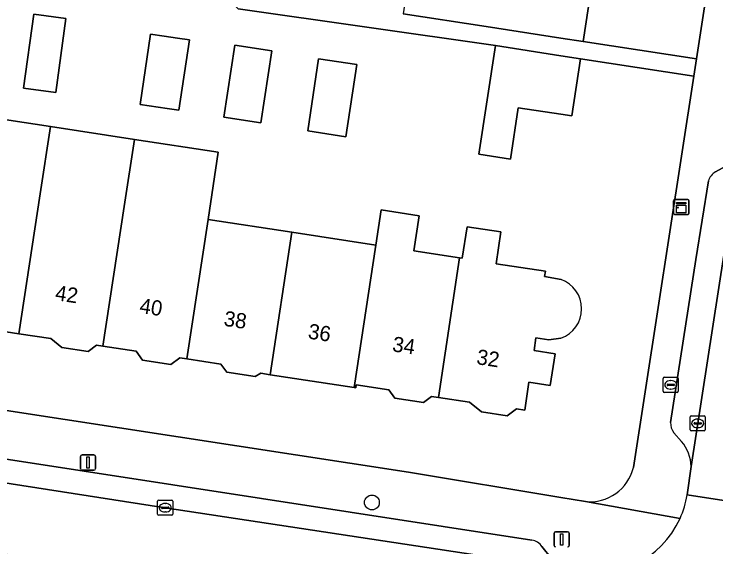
# Model space of a CAD drawing. Extents: x 161483 to 162250, y 379484 to 380833.
# Drawn here: x 161963.9 to 162010.23, y 380537.71 to 380572.87 of the extents above; entities that cross this region are included whole.
import ezdxf

# ---------------------------------------------------------------- set-up
doc = ezdxf.new("R2010")
doc.units = 0
for name, color, linetype in [('IMGEO_Boom', 7, 'Continuous'), ('IMGEO_Brandkraan', 7, 'Continuous'), ('IMGEO_Erf', 7, 'Continuous'), ('IMGEO_Kast', 7, 'Continuous'), ('IMGEO_Kolk', 7, 'Continuous'), ('IMGEO_Lichtmast', 7, 'Continuous'), ('IMGEO_Pand', 7, 'Continuous'), ('IMGEO_Pand_nummerreeks', 7, 'Continuous'), ('IMGEO_Parkeervlak_open', 7, 'Continuous'), ('IMGEO_Rijbaan_lokaal_open', 7, 'Continuous'), ('IMGEO_Voetpad_open', 7, 'Continuous')]:
    doc.layers.add(name, color=color, linetype=linetype)

msp = doc.modelspace()

# ---------------------------------------------------------------- linework, layer by layer
at = {"layer": 'IMGEO_Boom'}
msp.add_circle((161987.521, 380540.644), 0.489, dxfattribs=at)
at = {"layer": 'IMGEO_Brandkraan'}
for p, q in [((162006.744, 380547.979), (162006.744, 380548.831)), ((162006.819, 380548.905), (162007.671, 380548.905)), ((162007.745, 380548.831), (162007.745, 380547.979)), ((162007.003, 380548.399), (162007.003, 380548.411)), ((162007.441, 380548.362), (162007.043, 380548.362)), ((162007.046, 380548.448), (162007.444, 380548.448)), ((162007.232, 380548.685), (162007.257, 380548.685)), ((162007.487, 380548.411), (162007.487, 380548.399)), ((162007.671, 380547.905), (162006.819, 380547.905)), ((162007.255, 380548.125), (162007.23, 380548.125))]:
    msp.add_line(p, q, dxfattribs=at)
for points in [[(162006.744, 380547.979), (162006.744, 380548.831)], [(162006.819, 380548.905), (162007.671, 380548.905)], [(162007.745, 380548.831), (162007.745, 380547.979)], [(162007.671, 380547.905), (162006.819, 380547.905)]]:
    msp.add_lwpolyline(points, dxfattribs=at)
for centre, radius, start, end in [((162006.821, 380548.829), 0.0765, 91.552, 178.448), ((162006.821, 380548.829), 0.0765, 91.552, 178.448), ((162007.669, 380548.829), 0.0765, 1.552, 88.448), ((162007.669, 380548.829), 0.0765, 1.552, 88.448), ((162007.043, 380548.408), 0.0403, 85.8775, 175.7526), ((162007.04, 380548.398), 0.0366, 178.938, 274.7102), ((162007.444, 380548.405), 0.043, 264.8664, 352.4533), ((162007.448, 380548.41), 0.0386, 1.7309, 96.639), ((162006.821, 380547.981), 0.0765, 181.552, 268.448), ((162006.821, 380547.981), 0.0765, 181.552, 268.448), ((162007.669, 380547.981), 0.0765, 271.552, 358.448), ((162007.669, 380547.981), 0.0765, 271.552, 358.448)]:
    msp.add_arc(centre, radius, start, end, dxfattribs=at)
for centre, major_axis, ratio, start_param, end_param in [((162007.231, 380548.405), (-0.387, 0.002), 0.722429, 4.712389, 7.853982), ((162007.256, 380548.405), (-0.39, 0.002), 0.717154, 1.570796, 4.712389)]:
    msp.add_ellipse(centre, major_axis=major_axis, ratio=ratio, start_param=start_param, end_param=end_param, dxfattribs=at)
at = {"layer": 'IMGEO_Erf'}
for points in [[(162001.825, 380573.376), (162001.469, 380571.06), (162008.935, 380569.909), (162019.94, 380641.308)], [(162004.779, 380542.949), (162008.76, 380568.777), (162001.293, 380569.928), (162000.713, 380566.149), (162000, 380566.259), (161997.184, 380566.691), (161996.663, 380563.299), (161994.567, 380563.62), (161995.667, 380570.791), (161978.692, 380573.217), (161972.841, 380578.787), (161972.586, 380577.129), (161971.639, 380576.511), (161968.421, 380577.007), (161969.225, 380582.226), (161964.224, 380587.502), (161963.937, 380589.722), (161969.705, 380626.52)], [(161960.773, 380566.29), (161966.308, 380565.444), (161971.844, 380564.598), (161977.38, 380563.752), (161976.703, 380559.32), (161982.238, 380558.474), (161987.774, 380557.628), (161988.129, 380559.952), (161990.638, 380559.569), (161990.283, 380557.244), (161993.31, 380556.781), (161993.483, 380556.755), (161993.802, 380558.84), (161996.036, 380558.498), (161995.715, 380556.4), (161998.975, 380555.902), (161998.923, 380555.56), (162000.002, 380555.36)], [(162000, 380551.488), (161999.206, 380551.367), (161998.346, 380551.499), (161998.22, 380550.674), (161999.614, 380550.461), (161999.293, 380548.361), (161997.887, 380548.576), (161997.606, 380546.739), (161997.065, 380546.822), (161996.44, 380546.363), (161994.761, 380546.619), (161993.961, 380547.261), (161991.905, 380547.575), (161991.459, 380547.643), (161990.917, 380547.245), (161989.04, 380547.532), (161988.637, 380548.08), (161986.484, 380548.409), (161986.454, 380548.211), (161986.339, 380548.229), (161980.803, 380549.074), (161980.19, 380549.168), (161979.812, 380548.947), (161977.943, 380549.232), (161977.545, 380549.774), (161975.297, 380550.118), (161974.85, 380550.186), (161974.254, 380549.748), (161972.38, 380550.035), (161971.95, 380550.619), (161969.762, 380550.954), (161969.334, 380551.019), (161968.785, 380550.615), (161967.059, 380550.879), (161966.337, 380551.457), (161964.223, 380551.78), (161961.813, 380552.149)], [(161963.411, 380546.705), (161989.926, 380542.639), (162000, 380540.965), (162001.608, 380540.698)]]:
    msp.add_lwpolyline(points, dxfattribs=at)
for points in [[(161967.316, 380572.573), (161966.652, 380567.691), (161964.534, 380567.979), (161965.198, 380572.861)], [(161973.801, 380571.411), (161974.698, 380571.279), (161975.485, 380571.164), (161974.776, 380566.522), (161974.016, 380566.638), (161972.222, 380566.912), (161972.904, 380571.542)], [(161980.909, 380570.448), (161980.183, 380565.688), (161977.741, 380566.061), (161978.468, 380570.821)], [(161986.523, 380569.533), (161985.797, 380564.776), (161983.284, 380565.16), (161983.986, 380569.92)]]:
    msp.add_lwpolyline(points, close=True, dxfattribs=at)
for centre, radius, start, end in [((161999.303, 380553.424), 2.058, 289.7959, 70.1449), ((162001.886, 380543.666), 2.981, 264.6501, 346.0895)]:
    msp.add_arc(centre, radius, start, end, dxfattribs=at)
at = {"layer": 'IMGEO_Kast'}
for p, q in [((162007.436, 380559.713), (162007.436, 380560.554)), ((162007.436, 380560.554), (162007.436, 380559.713)), ((162007.511, 380560.638), (162008.352, 380560.638)), ((162008.352, 380560.638), (162007.511, 380560.638)), ((162008.436, 380560.563), (162008.436, 380559.722)), ((162008.436, 380559.722), (162008.436, 380560.563)), ((162008.361, 380559.638), (162007.52, 380559.638)), ((162007.52, 380559.638), (162008.361, 380559.638))]:
    msp.add_line(p, q, dxfattribs=at)
for points in [[(162007.631, 380560.428), (162008.231, 380560.428), (162008.231, 380560.343), (162007.631, 380560.343), (162007.631, 380560.428)], [(162007.631, 380560.253), (162008.231, 380560.253), (162008.231, 380559.764), (162007.631, 380559.764), (162007.631, 380560.253)]]:
    msp.add_lwpolyline(points, dxfattribs=at)
msp.add_circle((162007.715, 380560.102), 0.0377, dxfattribs=at)
for centre, start, end in [((162007.514, 380560.56), 92.4484, 184.2845), ((162007.514, 380560.56), 92.4484, 184.2845), ((162008.358, 380560.56), 2.4484, 94.2845), ((162008.358, 380560.56), 2.4484, 94.2845), ((162007.514, 380559.716), 182.4484, 274.2845), ((162007.514, 380559.716), 182.4484, 274.2845), ((162008.358, 380559.716), 272.4484, 4.2845), ((162008.358, 380559.716), 272.4484, 4.2845)]:
    msp.add_arc(centre, 0.0779, start, end, dxfattribs=at)
at = {"layer": 'IMGEO_Kolk'}
for p, q in [((162008.524, 380545.437), (162008.524, 380546.289)), ((162008.599, 380546.363), (162009.451, 380546.363)), ((162009.012, 380546.143), (162009.037, 380546.143)), ((162009.525, 380546.289), (162009.525, 380545.437)), ((162008.783, 380545.857), (162008.783, 380545.869)), ((162009.221, 380545.82), (162008.823, 380545.82)), ((162008.826, 380545.906), (162009.224, 380545.906)), ((162009.035, 380545.583), (162009.01, 380545.583)), ((162009.267, 380545.869), (162009.267, 380545.857)), ((162009.451, 380545.363), (162008.599, 380545.363)), ((161973.378, 380539.872), (161973.378, 380540.724)), ((161973.453, 380540.798), (161974.305, 380540.798)), ((161973.866, 380540.578), (161973.891, 380540.578)), ((161974.379, 380540.724), (161974.379, 380539.872)), ((161973.637, 380540.292), (161973.637, 380540.304)), ((161974.075, 380540.255), (161973.677, 380540.255)), ((161973.68, 380540.341), (161974.078, 380540.341)), ((161973.889, 380540.018), (161973.864, 380540.018)), ((161974.121, 380540.304), (161974.121, 380540.292)), ((161974.305, 380539.798), (161973.453, 380539.798))]:
    msp.add_line(p, q, dxfattribs=at)
for points in [[(162008.524, 380545.437), (162008.524, 380546.289)], [(162008.599, 380546.363), (162009.451, 380546.363)], [(162009.525, 380546.289), (162009.525, 380545.437)], [(162009.451, 380545.363), (162008.599, 380545.363)], [(161973.378, 380539.872), (161973.378, 380540.724)], [(161973.453, 380540.798), (161974.305, 380540.798)], [(161974.379, 380540.724), (161974.379, 380539.872)], [(161974.305, 380539.798), (161973.453, 380539.798)]]:
    msp.add_lwpolyline(points, dxfattribs=at)
for centre, radius, start, end in [((162008.601, 380546.287), 0.0765, 91.552, 178.448), ((162008.601, 380546.287), 0.0765, 91.552, 178.448), ((162009.449, 380546.287), 0.0765, 1.552, 88.448), ((162009.449, 380546.287), 0.0765, 1.552, 88.448), ((162008.823, 380545.866), 0.0403, 85.8775, 175.7526), ((162008.82, 380545.856), 0.0366, 178.938, 274.7102), ((162009.224, 380545.863), 0.043, 264.8664, 352.4533), ((162009.228, 380545.868), 0.0386, 1.7309, 96.639), ((162008.601, 380545.439), 0.0765, 181.552, 268.448), ((162008.601, 380545.439), 0.0765, 181.552, 268.448), ((162009.449, 380545.439), 0.0765, 271.552, 358.448), ((162009.449, 380545.439), 0.0765, 271.552, 358.448), ((161973.455, 380540.722), 0.0765, 91.552, 178.448), ((161973.455, 380540.722), 0.0765, 91.552, 178.448), ((161974.303, 380540.722), 0.0765, 1.552, 88.448), ((161974.303, 380540.722), 0.0765, 1.552, 88.448), ((161973.677, 380540.301), 0.0403, 85.8775, 175.7526), ((161973.674, 380540.291), 0.0366, 178.938, 274.7102), ((161974.078, 380540.298), 0.043, 264.8664, 352.4533), ((161974.082, 380540.303), 0.0386, 1.7309, 96.639), ((161973.455, 380539.874), 0.0765, 181.552, 268.448), ((161973.455, 380539.874), 0.0765, 181.552, 268.448), ((161974.303, 380539.874), 0.0765, 271.552, 358.448), ((161974.303, 380539.874), 0.0765, 271.552, 358.448)]:
    msp.add_arc(centre, radius, start, end, dxfattribs=at)
for centre, major_axis, ratio, start_param, end_param in [((162009.011, 380545.863), (-0.387, 0.002), 0.722429, 4.712389, 7.853982), ((162009.036, 380545.863), (-0.39, 0.002), 0.717154, 1.570796, 4.712389), ((161973.865, 380540.298), (-0.387, 0.002), 0.722429, 4.712389, 7.853982), ((161973.89, 380540.298), (-0.39, 0.002), 0.717154, 1.570796, 4.712389)]:
    msp.add_ellipse(centre, major_axis=major_axis, ratio=ratio, start_param=start_param, end_param=end_param, dxfattribs=at)
at = {"layer": 'IMGEO_Lichtmast'}
for p, q in [((161968.386, 380543.778), (161969.176, 380543.778)), ((161969.176, 380543.778), (161968.386, 380543.778)), ((161968.286, 380542.878), (161968.286, 380543.678)), ((161968.286, 380543.678), (161968.286, 380542.878)), ((161969.276, 380543.678), (161969.276, 380542.878)), ((161969.276, 380542.878), (161969.276, 380543.678)), ((161969.176, 380542.778), (161968.386, 380542.778)), ((161968.386, 380542.778), (161969.176, 380542.778)), ((161999.649, 380538.709), (162000.439, 380538.709)), ((162000.439, 380538.709), (161999.649, 380538.709)), ((161999.549, 380537.809), (161999.549, 380538.609)), ((161999.549, 380538.609), (161999.549, 380537.809)), ((162000.539, 380538.609), (162000.539, 380537.809)), ((162000.539, 380537.809), (162000.539, 380538.609))]:
    msp.add_line(p, q, dxfattribs=at)
for points in [[(161968.706, 380543.653), (161968.856, 380543.653), (161968.856, 380542.903), (161968.706, 380542.903), (161968.706, 380543.653)], [(161999.969, 380538.584), (162000.119, 380538.584), (162000.119, 380537.834), (161999.969, 380537.834), (161999.969, 380538.584)]]:
    msp.add_lwpolyline(points, dxfattribs=at)
for centre, start, end in [((161968.386, 380543.678), 90, 180), ((161968.386, 380543.678), 90, 180), ((161969.176, 380543.678), 0, 90), ((161969.176, 380543.678), 360, 90), ((161968.386, 380542.878), 180, 270), ((161968.386, 380542.878), 180, 270), ((161969.176, 380542.878), 270, 0), ((161969.176, 380542.878), 270, 0), ((161999.649, 380538.609), 90, 180), ((161999.649, 380538.609), 90, 180), ((162000.439, 380538.609), 0, 90), ((162000.439, 380538.609), 360, 90), ((161999.649, 380537.809), 180, 270), ((161999.649, 380537.809), 180, 270), ((162000.439, 380537.809), 270, 0), ((162000.439, 380537.809), 270, 0)]:
    msp.add_arc(centre, 0.1, start, end, dxfattribs=at)
at = {"layer": 'IMGEO_Pand'}
for points in [[(161990.423, 380578.414), (161989.575, 380572.885), (161995.058, 380572.043), (162000, 380571.285), (162001.469, 380571.06), (162001.825, 380573.376), (162002.444, 380574.149), (162002.708, 380575.867), (162002.312, 380576.406), (162002.35, 380576.655), (162000, 380577.017)], [(161967.316, 380572.573), (161965.198, 380572.861), (161964.534, 380567.979), (161966.652, 380567.691)], [(161973.801, 380571.411), (161972.904, 380571.542), (161972.222, 380566.912), (161974.016, 380566.638), (161974.776, 380566.522), (161975.485, 380571.164), (161974.698, 380571.279)], [(161980.183, 380565.688), (161980.909, 380570.448), (161978.468, 380570.821), (161977.741, 380566.061)], [(161996.663, 380563.299), (161997.184, 380566.691), (162000, 380566.259), (162000.713, 380566.149), (162001.293, 380569.928), (162000, 380570.126), (161995.667, 380570.791), (161994.567, 380563.62)], [(161986.523, 380569.533), (161983.986, 380569.92), (161983.284, 380565.16), (161985.797, 380564.776)], [(161965.632, 380561.012), (161966.308, 380565.444), (161960.773, 380566.29), (161960.096, 380561.858), (161958.691, 380552.655), (161958.972, 380552.612), (161959.396, 380552.036), (161961.269, 380551.749), (161961.813, 380552.149), (161964.223, 380551.78)], [(161971.168, 380560.166), (161971.844, 380564.598), (161966.308, 380565.444), (161965.632, 380561.012), (161964.223, 380551.78), (161966.337, 380551.457), (161967.059, 380550.879), (161968.785, 380550.615), (161969.334, 380551.019), (161969.762, 380550.954)], [(161976.703, 380559.32), (161977.38, 380563.752), (161971.844, 380564.598), (161971.168, 380560.166), (161969.762, 380550.954), (161971.95, 380550.619), (161972.38, 380550.035), (161974.254, 380549.748), (161974.85, 380550.186), (161975.297, 380550.118)], [(161993.31, 380556.781), (161990.283, 380557.244), (161990.638, 380559.569), (161988.129, 380559.952), (161987.774, 380557.628), (161986.339, 380548.229), (161986.454, 380548.211), (161986.484, 380548.409), (161988.637, 380548.08), (161989.04, 380547.532), (161990.917, 380547.245), (161991.459, 380547.643), (161991.905, 380547.575)], [(161982.238, 380558.474), (161976.703, 380559.32), (161975.297, 380550.118), (161977.545, 380549.774), (161977.943, 380549.232), (161979.812, 380548.947), (161980.19, 380549.168), (161980.803, 380549.074)], [(161987.774, 380557.628), (161982.238, 380558.474), (161980.803, 380549.074), (161986.339, 380548.229)]]:
    msp.add_lwpolyline(points, close=True, dxfattribs=at)
msp.add_lwpolyline([(162000.002, 380555.36), (161998.923, 380555.56), (161998.975, 380555.902), (161995.715, 380556.4), (161996.036, 380558.498), (161993.802, 380558.84), (161993.483, 380556.755), (161993.31, 380556.781), (161991.905, 380547.575), (161993.961, 380547.261), (161994.761, 380546.619), (161996.44, 380546.363), (161997.065, 380546.822), (161997.606, 380546.739), (161997.887, 380548.576), (161999.293, 380548.361), (161999.614, 380550.461), (161998.22, 380550.674), (161998.346, 380551.499), (161999.206, 380551.367), (162000, 380551.488)], dxfattribs=at)
msp.add_arc((161999.303, 380553.424), 2.058, 289.7959, 70.1449, dxfattribs=at)
at = {"layer": 'IMGEO_Parkeervlak_open'}
for points in [[(162008.586, 380543.018), (162011.818, 380563.929)], [(162011.077, 380562.943), (162010.202, 380562.452)], [(162009.726, 380561.874), (162008.908, 380556.667), (162007.238, 380545.927)], [(161998.077, 380538.155), (161932.83, 380548.205)], [(161929.69, 380547.086), (161933.264, 380546.55), (161935.372, 380546.247), (161952.528, 380543.603), (161973.878, 380540.297), (161995.793, 380536.963), (162000, 380536.329), (162000.684, 380536.226), (162000, 380536.452), (161999.367, 380536.946), (161998.747, 380537.733)], [(162007.452, 380545.237), (162007.963, 380544.661)]]:
    msp.add_lwpolyline(points, dxfattribs=at)
for centre, radius, start, end in [((162010.714, 380561.546), 1.041, 119.4485, 161.6066), ((162008.256, 380545.865), 1.02, 176.4917, 217.9703), ((162006.077, 380543.006), 2.509, 0.2643, 41.2676), ((161997.956, 380537.22), 0.943, 32.972, 82.6184)]:
    msp.add_arc(centre, radius, start, end, dxfattribs=at)
at = {"layer": 'IMGEO_Rijbaan_lokaal_open'}
for points in [[(162016.325, 380563.195), (162011.818, 380563.929), (162008.586, 380543.018), (162008.321, 380541.139), (162012.756, 380540.46), (162013.037, 380542.229), (162015.801, 380559.859)], [(161933.264, 380546.55), (161932.606, 380542.007), (161936.805, 380541.351), (161952.685, 380538.893), (161975.164, 380535.431), (161994.763, 380532.455), (161999.874, 380531.653), (162000, 380531.633), (162000, 380531.772), (162000.684, 380536.226), (162000, 380536.329), (161995.793, 380536.963), (161973.878, 380540.297), (161952.528, 380543.603), (161935.372, 380546.247)]]:
    msp.add_lwpolyline(points, close=True, dxfattribs=at)
msp.add_lwpolyline([(162012.756, 380540.46), (162008.321, 380541.139)], dxfattribs=at)
for centre, radius, start, end in [((162002.354, 380542.08), 6.041, 335.6868, 351.0372), ((162002.309, 380542.092), 6.087, 254.5191, 335.7592)]:
    msp.add_arc(centre, radius, start, end, dxfattribs=at)
at = {"layer": 'IMGEO_Voetpad_open'}
for points in [[(162024.675, 380722.269), (162024.102, 380718.247), (162024.026, 380717.715), (162031.542, 380716.615), (162030.496, 380709.789), (162020.445, 380644.581), (162019.94, 380641.308), (162008.935, 380569.909), (162008.76, 380568.777), (162004.779, 380542.949)], [(162007.859, 380539.593), (162001.608, 380540.698), (162000, 380540.965), (161989.926, 380542.639), (161963.411, 380546.705), (161933.1, 380551.357), (161926.533, 380552.341), (161923.744, 380552.759), (161920.738, 380553.21), (161887.994, 380558.235), (161850.616, 380563.993), (161845.302, 380564.812), (161842.113, 380565.304), (161840.43, 380565.564), (161785.522, 380574.037), (161759.686, 380578.007), (161759.209, 380578.08), (161755.449, 380578.66), (161754.33, 380578.833), (161724.808, 380583.386), (161711.262, 380585.528)], [(161978.692, 380573.217), (161995.667, 380570.791), (162000, 380570.126), (162001.293, 380569.928), (162008.76, 380568.777), (162008.935, 380569.909), (162001.469, 380571.06), (162000, 380571.285), (161995.058, 380572.043), (161989.575, 380572.885)], [(162010.202, 380562.452), (162011.077, 380562.943)], [(162007.238, 380545.927), (162008.908, 380556.667), (162009.726, 380561.874)], [(161932.83, 380548.205), (161998.077, 380538.155)], [(162007.963, 380544.661), (162007.452, 380545.237)], [(162008.321, 380541.139), (162008.586, 380543.018)], [(162001.608, 380540.698), (162007.859, 380539.593)], [(161998.747, 380537.733), (161999.367, 380536.946), (162000, 380536.452), (162000.684, 380536.226)]]:
    msp.add_lwpolyline(points, dxfattribs=at)
for centre, radius, start, end in [((162010.714, 380561.546), 1.041, 119.4485, 161.6066), ((162008.256, 380545.865), 1.02, 176.4917, 217.9703), ((162006.077, 380543.006), 2.509, 0.2643, 41.2676), ((162001.886, 380543.666), 2.981, 264.6501, 346.0895), ((162002.354, 380542.08), 6.041, 335.6868, 351.0372), ((162002.309, 380542.092), 6.087, 254.5191, 335.7592), ((161997.956, 380537.22), 0.943, 32.972, 82.6184)]:
    msp.add_arc(centre, radius, start, end, dxfattribs=at)

# ---------------------------------------------------------------- texts
at = {"layer": 'IMGEO_Pand_nummerreeks'}
for s, rotation, p in [('42', 351.3598, (161966.569, 380554.004)), ('40', 351.3598, (161972.138, 380553.158)), ('38', 351.3604, (161977.7, 380552.312)), ('36', 351.3604, (161983.26, 380551.468)), ('34', 351.3598, (161988.823, 380550.623)), ('32', 351.3604, (161994.383, 380549.778))]:
    msp.add_text(s, height=1, rotation=rotation, dxfattribs=at).set_placement(p)

doc.saveas('drawing.dxf')
